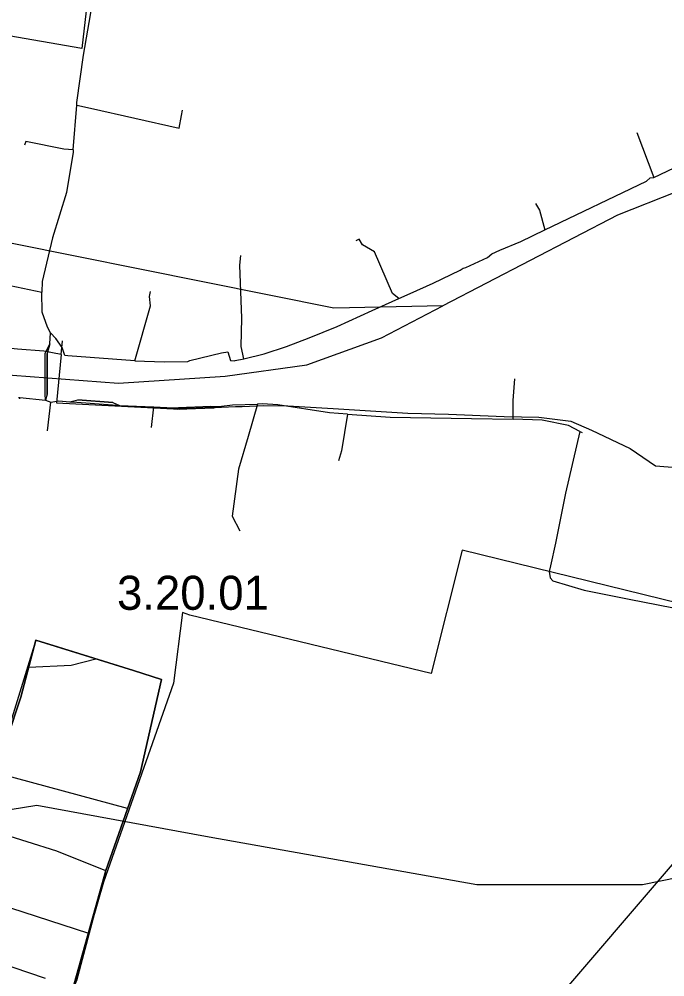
# Model space of a CAD drawing. Extents: x -662500 to -655523, y -1056000 to -1049993.
# Drawn here: x -660421.4 to -660279.1, y -1052282.8 to -1052071.9 of the extents above; entities that cross this region are included whole.
import ezdxf

# ---------------------------------------------------------------- set-up
doc = ezdxf.new("R2010")
doc.units = 0
for name, color, linetype in [('Vrstva 1', 7, 'Continuous'), ('Vrstva 20', 7, 'Continuous'), ('Vrstva 24', 7, 'Continuous'), ('Vrstva 45', 7, 'Continuous'), ('Vrstva 48', 7, 'Continuous'), ('Vrstva 5', 7, 'Continuous'), ('Vrstva 6', 7, 'Continuous'), ('Vrstva 7', 7, 'Continuous')]:
    doc.layers.add(name, color=color, linetype=linetype)

msp = doc.modelspace()

# ---------------------------------------------------------------- linework, layer by layer
at = {"layer": 'Vrstva 1'}
msp.add_lwpolyline([(-660408.77, -1052283.62), (-660402.29, -1052259.33), (-660394.65, -1052237.63), (-660389.99, -1052217.3), (-660396.18, -1052215.3), (-660414.84, -1052209.49), (-660417.67, -1052208.59), (-660421.03, -1052221.2), (-660427.21, -1052239.6), (-660428.58, -1052243.68), (-660452.47, -1052238.38), (-660475.36, -1052232.69), (-660497.36, -1052226.43)], dxfattribs=at)
at = {"layer": 'Vrstva 20'}
msp.add_lwpolyline([(-660611.17, -1052274.32), (-660487.99, -1052312.15), (-660486.82, -1052314.01), (-660462.36, -1052329.02), (-660459.17, -1052336.8), (-660433.93, -1052352.12), (-660408.77, -1052283.62), (-660402.29, -1052259.33), (-660394.65, -1052237.63), (-660389.99, -1052217.3), (-660417.67, -1052208.59), (-660428.58, -1052243.68), (-660475.36, -1052232.69), (-660499.48, -1052225.45), (-660495.07, -1052211.29), (-660578.14, -1052190.03), (-660563.85, -1052144.19), (-660586.5, -1052144.05), (-660704.06, -1052109.9), (-660743.35, -1052235.04)], close=True, dxfattribs=at)
at = {"layer": 'Vrstva 24'}
for points in [[(-660328, -1052135), (-660352, -1052135.5), (-660451.5, -1052115.5), (-660661, -1052057), (-660695, -1052042.5), (-660723, -1052024.5), (-660747.5, -1052000), (-660756.5, -1051991), (-660777.56, -1051972.71)], [(-660102.5, -1052161.5), (-660102.5, -1052154), (-660104, -1052141), (-660113.5, -1052125.5), (-660126, -1052110), (-660133.5, -1052104.5), (-660147, -1052098), (-660162, -1052094), (-660187.5, -1052090.5), (-660237.5, -1052094.5), (-660289.5, -1052115), (-660328, -1052135)], [(-660493, -1052145), (-660399.5, -1052152), (-660376, -1052150.5), (-660358, -1052148), (-660341.5, -1052142), (-660328, -1052135)], [(-660264.5, -1052258.5), (-660284, -1052262.5), (-660320.5, -1052262.5), (-660379.5, -1052252), (-660417.5, -1052245), (-660451.5, -1052250.5)]]:
    msp.add_lwpolyline(points, dxfattribs=at)
at = {"layer": 'Vrstva 45'}
for p, q in [((-660409.45, -1052100.6), (-660408.7, -1052090.8)), ((-660409.45, -1052100.6), (-660408.7, -1052090.8)), ((-660409.45, -1052100.6), (-660408.7, -1052090.8)), ((-660409.45, -1052100.6), (-660408.7, -1052090.8)), ((-660285.28, -1052096.78), (-660281.53, -1052106.71)), ((-660285.28, -1052096.78), (-660281.53, -1052106.71)), ((-660315.44, -1052122.7), (-660310.84, -1052120.8)), ((-660315.44, -1052122.7), (-660310.84, -1052120.8)), ((-660335.24, -1052132.24), (-660330.16, -1052129.96)), ((-660335.24, -1052132.24), (-660330.16, -1052129.96)), ((-660343.57, -1052136.03), (-660337.69, -1052133.38)), ((-660343.57, -1052136.03), (-660337.69, -1052133.38)), ((-660414.61, -1052143.32), (-660414.46, -1052140.93)), ((-660414.61, -1052143.32), (-660414.46, -1052140.93)), ((-660414.61, -1052143.32), (-660414.46, -1052140.93)), ((-660414.61, -1052143.32), (-660414.46, -1052140.93)), ((-660414.46, -1052140.93), (-660413.28, -1052142.15)), ((-660414.46, -1052140.93), (-660413.28, -1052142.15)), ((-660414.46, -1052140.93), (-660413.28, -1052142.15)), ((-660414.46, -1052140.93), (-660413.28, -1052142.15)), ((-660357.45, -1052142.04), (-660351.29, -1052139.56)), ((-660357.45, -1052142.04), (-660351.29, -1052139.56)), ((-660413.28, -1052142.15), (-660413.15, -1052142.16)), ((-660413.28, -1052142.15), (-660413.15, -1052142.16)), ((-660413.28, -1052142.15), (-660413.15, -1052142.16)), ((-660413.28, -1052142.15), (-660413.15, -1052142.16)), ((-660412.15, -1052145.73), (-660411.84, -1052142.72)), ((-660412.15, -1052145.73), (-660411.84, -1052142.72)), ((-660415.67, -1052154.38), (-660415.63, -1052145.48)), ((-660415.67, -1052154.38), (-660415.63, -1052145.48)), ((-660415.23, -1052154.43), (-660415.22, -1052145.47)), ((-660415.23, -1052154.43), (-660415.22, -1052145.47)), ((-660395.86, -1052147.1), (-660389.4, -1052147.3)), ((-660395.86, -1052147.1), (-660389.4, -1052147.3)), ((-660383.74, -1052147.01), (-660376.78, -1052145.3)), ((-660383.74, -1052147.01), (-660376.78, -1052145.3)), ((-660421.53, -1052155.16), (-660421.22, -1052155.19)), ((-660421.53, -1052155.16), (-660421.22, -1052155.19)), ((-660421.24, -1052155.49), (-660421.22, -1052155.19)), ((-660421.24, -1052155.49), (-660421.22, -1052155.19)), ((-660421.22, -1052155.19), (-660415.55, -1052155.73)), ((-660421.22, -1052155.19), (-660415.55, -1052155.73)), ((-660400.73, -1052156.27), (-660408.48, -1052155.7)), ((-660400.73, -1052156.27), (-660408.48, -1052155.7)), ((-660415.55, -1052155.73), (-660414.38, -1052156.21)), ((-660415.55, -1052155.73), (-660414.38, -1052156.21)), ((-660415.55, -1052155.73), (-660414.38, -1052156.21)), ((-660415.55, -1052155.73), (-660414.38, -1052156.21)), ((-660415.16, -1052162.49), (-660414.38, -1052156.21)), ((-660415.16, -1052162.49), (-660414.38, -1052156.21)), ((-660408.67, -1052156.23), (-660400.79, -1052156.82)), ((-660408.67, -1052156.23), (-660400.79, -1052156.82)), ((-660399.25, -1052156.91), (-660391.69, -1052157.24)), ((-660399.25, -1052156.91), (-660391.69, -1052157.24)), ((-660399.25, -1052156.91), (-660391.69, -1052157.24)), ((-660399.25, -1052156.91), (-660391.69, -1052157.24)), ((-660392.21, -1052161.8), (-660391.69, -1052157.24)), ((-660392.21, -1052161.8), (-660391.69, -1052157.24)), ((-660391.69, -1052157.24), (-660387.41, -1052157.44)), ((-660391.69, -1052157.24), (-660387.41, -1052157.44)), ((-660391.69, -1052157.24), (-660387.41, -1052157.44)), ((-660391.69, -1052157.24), (-660387.41, -1052157.44)), ((-660378.45, -1052157.45), (-660386.48, -1052157.76)), ((-660378.45, -1052157.45), (-660386.48, -1052157.76)), ((-660379.12, -1052157.16), (-660386.3, -1052157.46)), ((-660379.12, -1052157.16), (-660386.3, -1052157.46)), ((-660362.2, -1052157.04), (-660352.16, -1052157.62)), ((-660362.2, -1052157.04), (-660352.16, -1052157.62)), ((-660312.48, -1052159.92), (-660312.5, -1052155.85)), ((-660312.48, -1052159.92), (-660312.5, -1052155.85)), ((-660297.83, -1052162.63), (-660297.3, -1052162.85)), ((-660297.83, -1052162.63), (-660297.3, -1052162.85))]:
    msp.add_line(p, q, dxfattribs=at)
for points in [[(-660408.7, -1052090.8), (-660408.7, -1052090.2), (-660407.19, -1052079.76), (-660405.32, -1052068.75), (-660405.1, -1052066.69)], [(-660408.7, -1052090.8), (-660408.7, -1052090.2), (-660407.19, -1052079.76), (-660405.32, -1052068.75), (-660405.1, -1052066.69)], [(-660408.7, -1052090.8), (-660408.7, -1052090.2), (-660407.19, -1052079.76), (-660405.32, -1052068.75), (-660405.1, -1052066.69)], [(-660408.7, -1052090.8), (-660408.7, -1052090.2), (-660407.19, -1052079.76), (-660405.32, -1052068.75), (-660405.1, -1052066.69)], [(-660408.7, -1052090.8), (-660405.66, -1052091.48), (-660386.15, -1052095.84), (-660385.59, -1052093.08), (-660385.36, -1052091.89)], [(-660408.7, -1052090.8), (-660405.66, -1052091.48), (-660386.15, -1052095.84), (-660385.59, -1052093.08), (-660385.36, -1052091.89)], [(-660281.53, -1052106.71), (-660277.04, -1052104.59), (-660269.5, -1052101.18), (-660261.07, -1052097.42), (-660257.58, -1052096.09)], [(-660281.53, -1052106.71), (-660277.04, -1052104.59), (-660269.5, -1052101.18), (-660261.07, -1052097.42), (-660257.58, -1052096.09)], [(-660409.45, -1052100.6), (-660411.57, -1052100.48), (-660419.94, -1052098.78), (-660420.18, -1052099.59)], [(-660409.45, -1052100.6), (-660411.57, -1052100.48), (-660419.94, -1052098.78), (-660420.18, -1052099.59)], [(-660409.45, -1052100.6), (-660409.46, -1052101.13), (-660410.98, -1052110.03), (-660414.04, -1052120.04), (-660416.32, -1052129.63), (-660416.38, -1052131.95)], [(-660409.45, -1052100.6), (-660409.46, -1052101.13), (-660410.98, -1052110.03), (-660414.04, -1052120.04), (-660416.32, -1052129.63), (-660416.38, -1052131.95)], [(-660409.45, -1052100.6), (-660409.46, -1052101.13), (-660410.98, -1052110.03), (-660414.04, -1052120.04), (-660416.32, -1052129.63), (-660416.38, -1052131.95)], [(-660409.45, -1052100.6), (-660409.46, -1052101.13), (-660410.98, -1052110.03), (-660414.04, -1052120.04), (-660416.32, -1052129.63), (-660416.38, -1052131.95)], [(-660305.52, -1052118.24), (-660283.13, -1052107.55), (-660282.3, -1052106.78), (-660281.53, -1052106.71)], [(-660305.52, -1052118.24), (-660283.13, -1052107.55), (-660282.3, -1052106.78), (-660281.53, -1052106.71)], [(-660307.57, -1052112.43), (-660306.69, -1052113.89), (-660305.52, -1052118.24)], [(-660307.57, -1052112.43), (-660306.69, -1052113.89), (-660305.52, -1052118.24)], [(-660337.69, -1052133.38), (-660335.24, -1052132.24), (-660330.16, -1052129.96), (-660324.16, -1052127.1), (-660323.53, -1052126.67), (-660322.96, -1052126.55), (-660318.16, -1052124.36), (-660317.18, -1052123.53), (-660315.44, -1052122.7), (-660310.84, -1052120.8), (-660305.52, -1052118.24)], [(-660337.69, -1052133.38), (-660335.24, -1052132.24), (-660330.16, -1052129.96), (-660324.16, -1052127.1), (-660323.53, -1052126.67), (-660322.96, -1052126.55), (-660318.16, -1052124.36), (-660317.18, -1052123.53), (-660315.44, -1052122.7), (-660310.84, -1052120.8), (-660305.52, -1052118.24)], [(-660337.69, -1052133.38), (-660339.09, -1052132.26), (-660343.06, -1052123.07), (-660345.71, -1052121.54), (-660346.48, -1052120.29), (-660347.19, -1052120.65)], [(-660337.69, -1052133.38), (-660339.09, -1052132.26), (-660343.06, -1052123.07), (-660345.71, -1052121.54), (-660346.48, -1052120.29), (-660347.19, -1052120.65)], [(-660459.7, -1052124.03), (-660456.15, -1052124.67), (-660449.9, -1052125.06), (-660441.55, -1052126.88), (-660430.39, -1052129.05), (-660416.38, -1052131.95)], [(-660459.7, -1052124.03), (-660456.15, -1052124.67), (-660449.9, -1052125.06), (-660441.55, -1052126.88), (-660430.39, -1052129.05), (-660416.38, -1052131.95)], [(-660371.84, -1052146.69), (-660372.47, -1052143.93), (-660372.32, -1052137.7), (-660372.73, -1052126.06), (-660372.52, -1052123.9)], [(-660371.84, -1052146.69), (-660372.47, -1052143.93), (-660372.32, -1052137.7), (-660372.73, -1052126.06), (-660372.52, -1052123.9)], [(-660414.46, -1052140.93), (-660415.17, -1052139.69), (-660416.3, -1052136.39), (-660416.38, -1052131.95)], [(-660414.46, -1052140.93), (-660415.17, -1052139.69), (-660416.3, -1052136.39), (-660416.38, -1052131.95)], [(-660414.46, -1052140.93), (-660415.17, -1052139.69), (-660416.3, -1052136.39), (-660416.38, -1052131.95)], [(-660414.46, -1052140.93), (-660415.17, -1052139.69), (-660416.3, -1052136.39), (-660416.38, -1052131.95)], [(-660395.86, -1052147.1), (-660392.4, -1052135.02), (-660392.66, -1052132.92), (-660392.41, -1052131.85)], [(-660395.86, -1052147.1), (-660392.4, -1052135.02), (-660392.66, -1052132.92), (-660392.41, -1052131.85)], [(-660371.84, -1052146.69), (-660367.41, -1052145.57), (-660362.45, -1052143.97), (-660357.45, -1052142.04), (-660351.29, -1052139.56), (-660343.57, -1052136.03), (-660337.69, -1052133.38)], [(-660371.84, -1052146.69), (-660367.41, -1052145.57), (-660362.45, -1052143.97), (-660357.45, -1052142.04), (-660351.29, -1052139.56), (-660343.57, -1052136.03), (-660337.69, -1052133.38)], [(-660412.15, -1052145.73), (-660415.93, -1052144.97), (-660421.76, -1052144.56), (-660443.11, -1052142.49)], [(-660412.15, -1052145.73), (-660415.93, -1052144.97), (-660421.76, -1052144.56), (-660443.11, -1052142.49)], [(-660395.86, -1052147.1), (-660410.66, -1052146.01), (-660411.32, -1052145.93), (-660411.9, -1052144.14), (-660413.28, -1052142.15)], [(-660395.86, -1052147.1), (-660410.66, -1052146.01), (-660411.32, -1052145.93), (-660411.9, -1052144.14), (-660413.28, -1052142.15)], [(-660415.55, -1052155.73), (-660415.67, -1052154.38), (-660415.63, -1052145.48), (-660414.61, -1052143.32)], [(-660415.55, -1052155.73), (-660415.67, -1052154.38), (-660415.63, -1052145.48), (-660414.61, -1052143.32)], [(-660414.61, -1052143.32), (-660415.22, -1052145.47), (-660415.23, -1052154.43), (-660415.55, -1052155.73)], [(-660414.61, -1052143.32), (-660415.22, -1052145.47), (-660415.23, -1052154.43), (-660415.55, -1052155.73)], [(-660395.86, -1052147.1), (-660389.4, -1052147.3), (-660384.24, -1052147.22), (-660383.74, -1052147.01), (-660376.78, -1052145.3), (-660375.37, -1052145.15), (-660374.79, -1052147.04), (-660373.91, -1052147.12), (-660373.75, -1052147.05), (-660371.84, -1052146.69)], [(-660395.86, -1052147.1), (-660389.4, -1052147.3), (-660384.24, -1052147.22), (-660383.74, -1052147.01), (-660376.78, -1052145.3), (-660375.37, -1052145.15), (-660374.79, -1052147.04), (-660373.91, -1052147.12), (-660373.75, -1052147.05), (-660371.84, -1052146.69)], [(-660412.15, -1052145.73), (-660413.13, -1052156.36), (-660385.96, -1052157.72), (-660373.68, -1052157.19), (-660372.23, -1052157.15)], [(-660412.15, -1052145.73), (-660413.13, -1052156.36), (-660385.96, -1052157.72), (-660373.68, -1052157.19), (-660372.23, -1052157.15)], [(-660312.48, -1052159.92), (-660312.5, -1052155.85), (-660312.14, -1052151.06)], [(-660312.48, -1052159.92), (-660312.5, -1052155.85), (-660312.14, -1052151.06)], [(-660410.2, -1052156.13), (-660408.48, -1052155.7), (-660400.73, -1052156.27), (-660399.25, -1052156.91)], [(-660410.2, -1052156.13), (-660408.48, -1052155.7), (-660400.73, -1052156.27), (-660399.25, -1052156.91)], [(-660414.38, -1052156.21), (-660412.65, -1052155.91), (-660410.2, -1052156.13)], [(-660414.38, -1052156.21), (-660412.65, -1052155.91), (-660410.2, -1052156.13)], [(-660414.38, -1052156.21), (-660412.65, -1052155.91), (-660410.2, -1052156.13)], [(-660414.38, -1052156.21), (-660412.65, -1052155.91), (-660410.2, -1052156.13)], [(-660410.2, -1052156.13), (-660408.67, -1052156.23), (-660400.79, -1052156.82), (-660399.25, -1052156.91)], [(-660410.2, -1052156.13), (-660408.67, -1052156.23), (-660400.79, -1052156.82), (-660399.25, -1052156.91)], [(-660387.41, -1052157.44), (-660386.48, -1052157.76), (-660378.45, -1052157.45), (-660377.38, -1052157.14)], [(-660387.41, -1052157.44), (-660386.3, -1052157.46), (-660379.12, -1052157.16), (-660377.38, -1052157.14)], [(-660387.41, -1052157.44), (-660386.48, -1052157.76), (-660378.45, -1052157.45), (-660377.38, -1052157.14)], [(-660387.41, -1052157.44), (-660386.3, -1052157.46), (-660379.12, -1052157.16), (-660377.38, -1052157.14)], [(-660377.38, -1052157.14), (-660374.33, -1052156.77), (-660368.83, -1052156.61)], [(-660377.38, -1052157.14), (-660374.33, -1052156.77), (-660368.83, -1052156.61)], [(-660377.38, -1052157.14), (-660374.33, -1052156.77), (-660368.83, -1052156.61)], [(-660377.38, -1052157.14), (-660374.33, -1052156.77), (-660368.83, -1052156.61)], [(-660368.83, -1052156.61), (-660370.91, -1052163.74), (-660373.07, -1052170.94), (-660374.45, -1052181.29), (-660372.76, -1052184.55)], [(-660368.83, -1052156.61), (-660370.91, -1052163.74), (-660373.07, -1052170.94), (-660374.45, -1052181.29), (-660372.76, -1052184.55)], [(-660372.23, -1052157.15), (-660367.47, -1052156.91), (-660362.2, -1052157.04)], [(-660372.23, -1052157.15), (-660367.47, -1052156.91), (-660362.2, -1052157.04)], [(-660349.05, -1052158.82), (-660352.99, -1052158.54), (-660364.35, -1052156.82), (-660367.76, -1052156.58), (-660368.83, -1052156.61)], [(-660349.05, -1052158.82), (-660352.99, -1052158.54), (-660364.35, -1052156.82), (-660367.76, -1052156.58), (-660368.83, -1052156.61)], [(-660349.05, -1052158.82), (-660352.99, -1052158.54), (-660364.35, -1052156.82), (-660367.76, -1052156.58), (-660368.83, -1052156.61)], [(-660349.05, -1052158.82), (-660352.99, -1052158.54), (-660364.35, -1052156.82), (-660367.76, -1052156.58), (-660368.83, -1052156.61)], [(-660352.16, -1052157.62), (-660335.69, -1052158.64), (-660326.78, -1052158.82)], [(-660352.16, -1052157.62), (-660335.69, -1052158.64), (-660326.78, -1052158.82)], [(-660406.92, -1052407.55), (-660363.86, -1052404.75), (-660353.26, -1052407.03), (-660354.37, -1052405.55), (-660346.36, -1052338.47), (-660234.76, -1052208.31), (-660228.59, -1052182.33), (-660225.54, -1052166.06), (-660224.19, -1052158.96)], [(-660406.92, -1052407.55), (-660363.86, -1052404.75), (-660353.26, -1052407.03), (-660354.37, -1052405.55), (-660346.36, -1052338.47), (-660234.76, -1052208.31), (-660228.59, -1052182.33), (-660225.54, -1052166.06), (-660224.19, -1052158.96)], [(-660349.05, -1052158.82), (-660350.34, -1052166.92), (-660350.99, -1052169.15)], [(-660349.05, -1052158.82), (-660350.34, -1052166.92), (-660350.99, -1052169.15)], [(-660349.05, -1052158.82), (-660339.65, -1052159.47), (-660321.71, -1052159.83), (-660312.48, -1052159.92)], [(-660349.05, -1052158.82), (-660339.65, -1052159.47), (-660321.71, -1052159.83), (-660312.48, -1052159.92)], [(-660349.05, -1052158.82), (-660339.65, -1052159.47), (-660321.71, -1052159.83), (-660312.48, -1052159.92)], [(-660349.05, -1052158.82), (-660339.65, -1052159.47), (-660321.71, -1052159.83), (-660312.48, -1052159.92)], [(-660326.78, -1052158.82), (-660314.49, -1052159.38), (-660306.83, -1052159.48), (-660299.77, -1052160.36), (-660295.24, -1052162.37), (-660286.72, -1052166.43), (-660281.12, -1052170.24), (-660269.16, -1052171.2)], [(-660326.78, -1052158.82), (-660314.49, -1052159.38), (-660306.83, -1052159.48), (-660299.77, -1052160.36), (-660295.24, -1052162.37), (-660286.72, -1052166.43), (-660281.12, -1052170.24), (-660269.16, -1052171.2)], [(-660297.83, -1052162.63), (-660300.32, -1052161.32), (-660306.13, -1052160.13), (-660312.48, -1052159.92)], [(-660297.83, -1052162.63), (-660300.32, -1052161.32), (-660306.13, -1052160.13), (-660312.48, -1052159.92)], [(-660297.83, -1052162.63), (-660300.32, -1052161.32), (-660306.13, -1052160.13), (-660312.48, -1052159.92)], [(-660297.83, -1052162.63), (-660300.32, -1052161.32), (-660306.13, -1052160.13), (-660312.48, -1052159.92)], [(-660297.83, -1052162.63), (-660301, -1052176.24), (-660303.17, -1052187.25), (-660304.28, -1052192.23), (-660304.61, -1052193.51), (-660304.38, -1052194.88), (-660303.77, -1052195.55), (-660296.85, -1052197.57), (-660286.96, -1052199.58), (-660270.75, -1052202.75), (-660257.72, -1052205.38), (-660243.47, -1052208.14), (-660238.67, -1052208.97), (-660237.25, -1052208.73), (-660236.68, -1052208.05), (-660235.91, -1052205.63), (-660234.14, -1052196.53)], [(-660297.83, -1052162.63), (-660301, -1052176.24), (-660303.17, -1052187.25), (-660304.28, -1052192.23), (-660304.61, -1052193.51), (-660304.38, -1052194.88), (-660303.77, -1052195.55), (-660296.85, -1052197.57), (-660286.96, -1052199.58), (-660270.75, -1052202.75), (-660257.72, -1052205.38), (-660243.47, -1052208.14), (-660238.67, -1052208.97), (-660237.25, -1052208.73), (-660236.68, -1052208.05), (-660235.91, -1052205.63), (-660234.14, -1052196.53)], [(-660297.83, -1052162.63), (-660301, -1052176.24), (-660303.17, -1052187.25), (-660304.28, -1052192.23), (-660304.61, -1052193.51), (-660304.38, -1052194.88), (-660303.77, -1052195.55), (-660296.85, -1052197.57), (-660286.96, -1052199.58), (-660270.75, -1052202.75), (-660257.72, -1052205.38), (-660243.47, -1052208.14), (-660238.67, -1052208.97), (-660237.25, -1052208.73), (-660236.68, -1052208.05), (-660235.91, -1052205.63), (-660234.14, -1052196.53)], [(-660297.83, -1052162.63), (-660301, -1052176.24), (-660303.17, -1052187.25), (-660304.28, -1052192.23), (-660304.61, -1052193.51), (-660304.38, -1052194.88), (-660303.77, -1052195.55), (-660296.85, -1052197.57), (-660286.96, -1052199.58), (-660270.75, -1052202.75), (-660257.72, -1052205.38), (-660243.47, -1052208.14), (-660238.67, -1052208.97), (-660237.25, -1052208.73), (-660236.68, -1052208.05), (-660235.91, -1052205.63), (-660234.14, -1052196.53)]]:
    msp.add_lwpolyline(points, dxfattribs=at)
at = {"layer": 'Vrstva 48'}
for points in [[(-660538.48, -1052060.8), (-660532.95, -1052023.05), (-660419.09, -1051950.78), (-660293.14, -1051956.25), (-660296.06, -1052023.47), (-660343.35, -1052021.42), (-660365.15, -1052017.09), (-660400.6, -1052017.74), (-660407.59, -1052078.33), (-660450.39, -1052070.9), (-660455.11, -1052085.25), (-660475.19, -1052077.7), (-660472.89, -1052072.61), (-660501.35, -1052043.96), (-660517.23, -1052041.74), (-660522.98, -1052061.96), (-660537.85, -1052062.06)], [(-660235.74, -1052210.41), (-660323.75, -1052188.77), (-660330.58, -1052215.92), (-660383.74, -1052203.08), (-660385.39, -1052202.51), (-660387.33, -1052218.12), (-660402.76, -1052261.89), (-660409.6, -1052285.62), (-660433.96, -1052352.54), (-660433.69, -1052354.11), (-660488.03, -1052323.42), (-660486.09, -1052324.83), (-660552.87, -1052466.56), (-660541.03, -1052517.76), (-660486.65, -1052503.76), (-660522.33, -1052569.27), (-660272.98, -1052680.64)]]:
    msp.add_lwpolyline(points, dxfattribs=at)
at = {"layer": 'Vrstva 5'}
msp.add_lwpolyline([(-660757.57, -1052084.94), (-660618.97, -1052129.25), (-660588.97, -1052137.76), (-660563.85, -1052144.19), (-660578.14, -1052190.03), (-660527.17, -1052203.32), (-660495.07, -1052211.29), (-660499.48, -1052225.45), (-660497.36, -1052226.43), (-660475.36, -1052232.69), (-660428.58, -1052243.68), (-660421.03, -1052221.2), (-660417.67, -1052208.59), (-660396.18, -1052215.3), (-660389.99, -1052217.3), (-660394.65, -1052237.63), (-660402.29, -1052259.33), (-660408.77, -1052283.62)], dxfattribs=at)
at = {"layer": 'Vrstva 6'}
msp.add_lwpolyline([(-660462.36, -1052329.02), (-660459.17, -1052336.8), (-660433.93, -1052352.12), (-660409.6, -1052285.62), (-660402.29, -1052259.33), (-660394.65, -1052237.63), (-660389.99, -1052217.3), (-660417.67, -1052208.59), (-660421.03, -1052221.2), (-660428.58, -1052243.68), (-660452.47, -1052238.38), (-660475.36, -1052232.69), (-660499.48, -1052225.45), (-660495.07, -1052211.29), (-660578.14, -1052190.03), (-660563.85, -1052144.19), (-660586.5, -1052144.05), (-660704.06, -1052109.9), (-660743.35, -1052235.04), (-661096.01, -1052128.52), (-661110.22, -1052170.21), (-660506.09, -1052352.23), (-660487.99, -1052312.15)], close=True, dxfattribs=at)
at = {"layer": 'Vrstva 7'}
for p, q in [((-660419.26, -1052214.55), (-660409.93, -1052214.09)), ((-660409.93, -1052214.09), (-660404.46, -1052212.72)), ((-660397.48, -1052245.66), (-660425.8, -1052238.04)), ((-660413.05, -1052255.11), (-660446.14, -1052244.77)), ((-660402.31, -1052259.4), (-660413.05, -1052255.11)), ((-660406, -1052273.22), (-660439.41, -1052262.41)), ((-660415.6, -1052283.1), (-660444.79, -1052273.32))]:
    msp.add_line(p, q, dxfattribs=at)

# ---------------------------------------------------------------- texts
at = {"layer": 'Vrstva 24'}
msp.add_text('3.20.01', height=7.5, dxfattribs=at).set_placement((-660399.81, -1052201.93))

doc.saveas('drawing.dxf')
